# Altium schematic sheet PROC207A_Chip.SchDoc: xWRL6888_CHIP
size 431 x 279 mm; Date: Not shown in title block; ApprovedBy: Not shown in title block; CheckedBy: Not shown in title block; Author: Not shown in title block; CompanyName: Not shown in title block; DrawnBy: Mistral; Engineer: Not shown in title block; Organization: Not shown in title block; Address1: Not shown in title block; Address2: Not shown in title block; Address3: Not shown in title block; Address4: Not shown in title block; DocumentNumber: 1; Revision: Use project parameter SCH_Rev; SheetNumber: 6; SheetTotal: 18; PageSetup: Record=PageOptions¦CenterHorizontal=True¦CenterVertical=True¦PrintScale=1.00¦XCorrection=1.00¦YCorrection=1.00¦PrintKind=0¦BorderSize=5000000¦LeftOffset=0¦BottomOffset=0¦Orientation=2¦PaperLength=1000¦PaperWidth=1000¦Scale=100¦PaperSource=15¦PrintQuality=600¦MediaType=1¦DitherType=10¦PaperKind=Letter¦PrintScaleMode=1
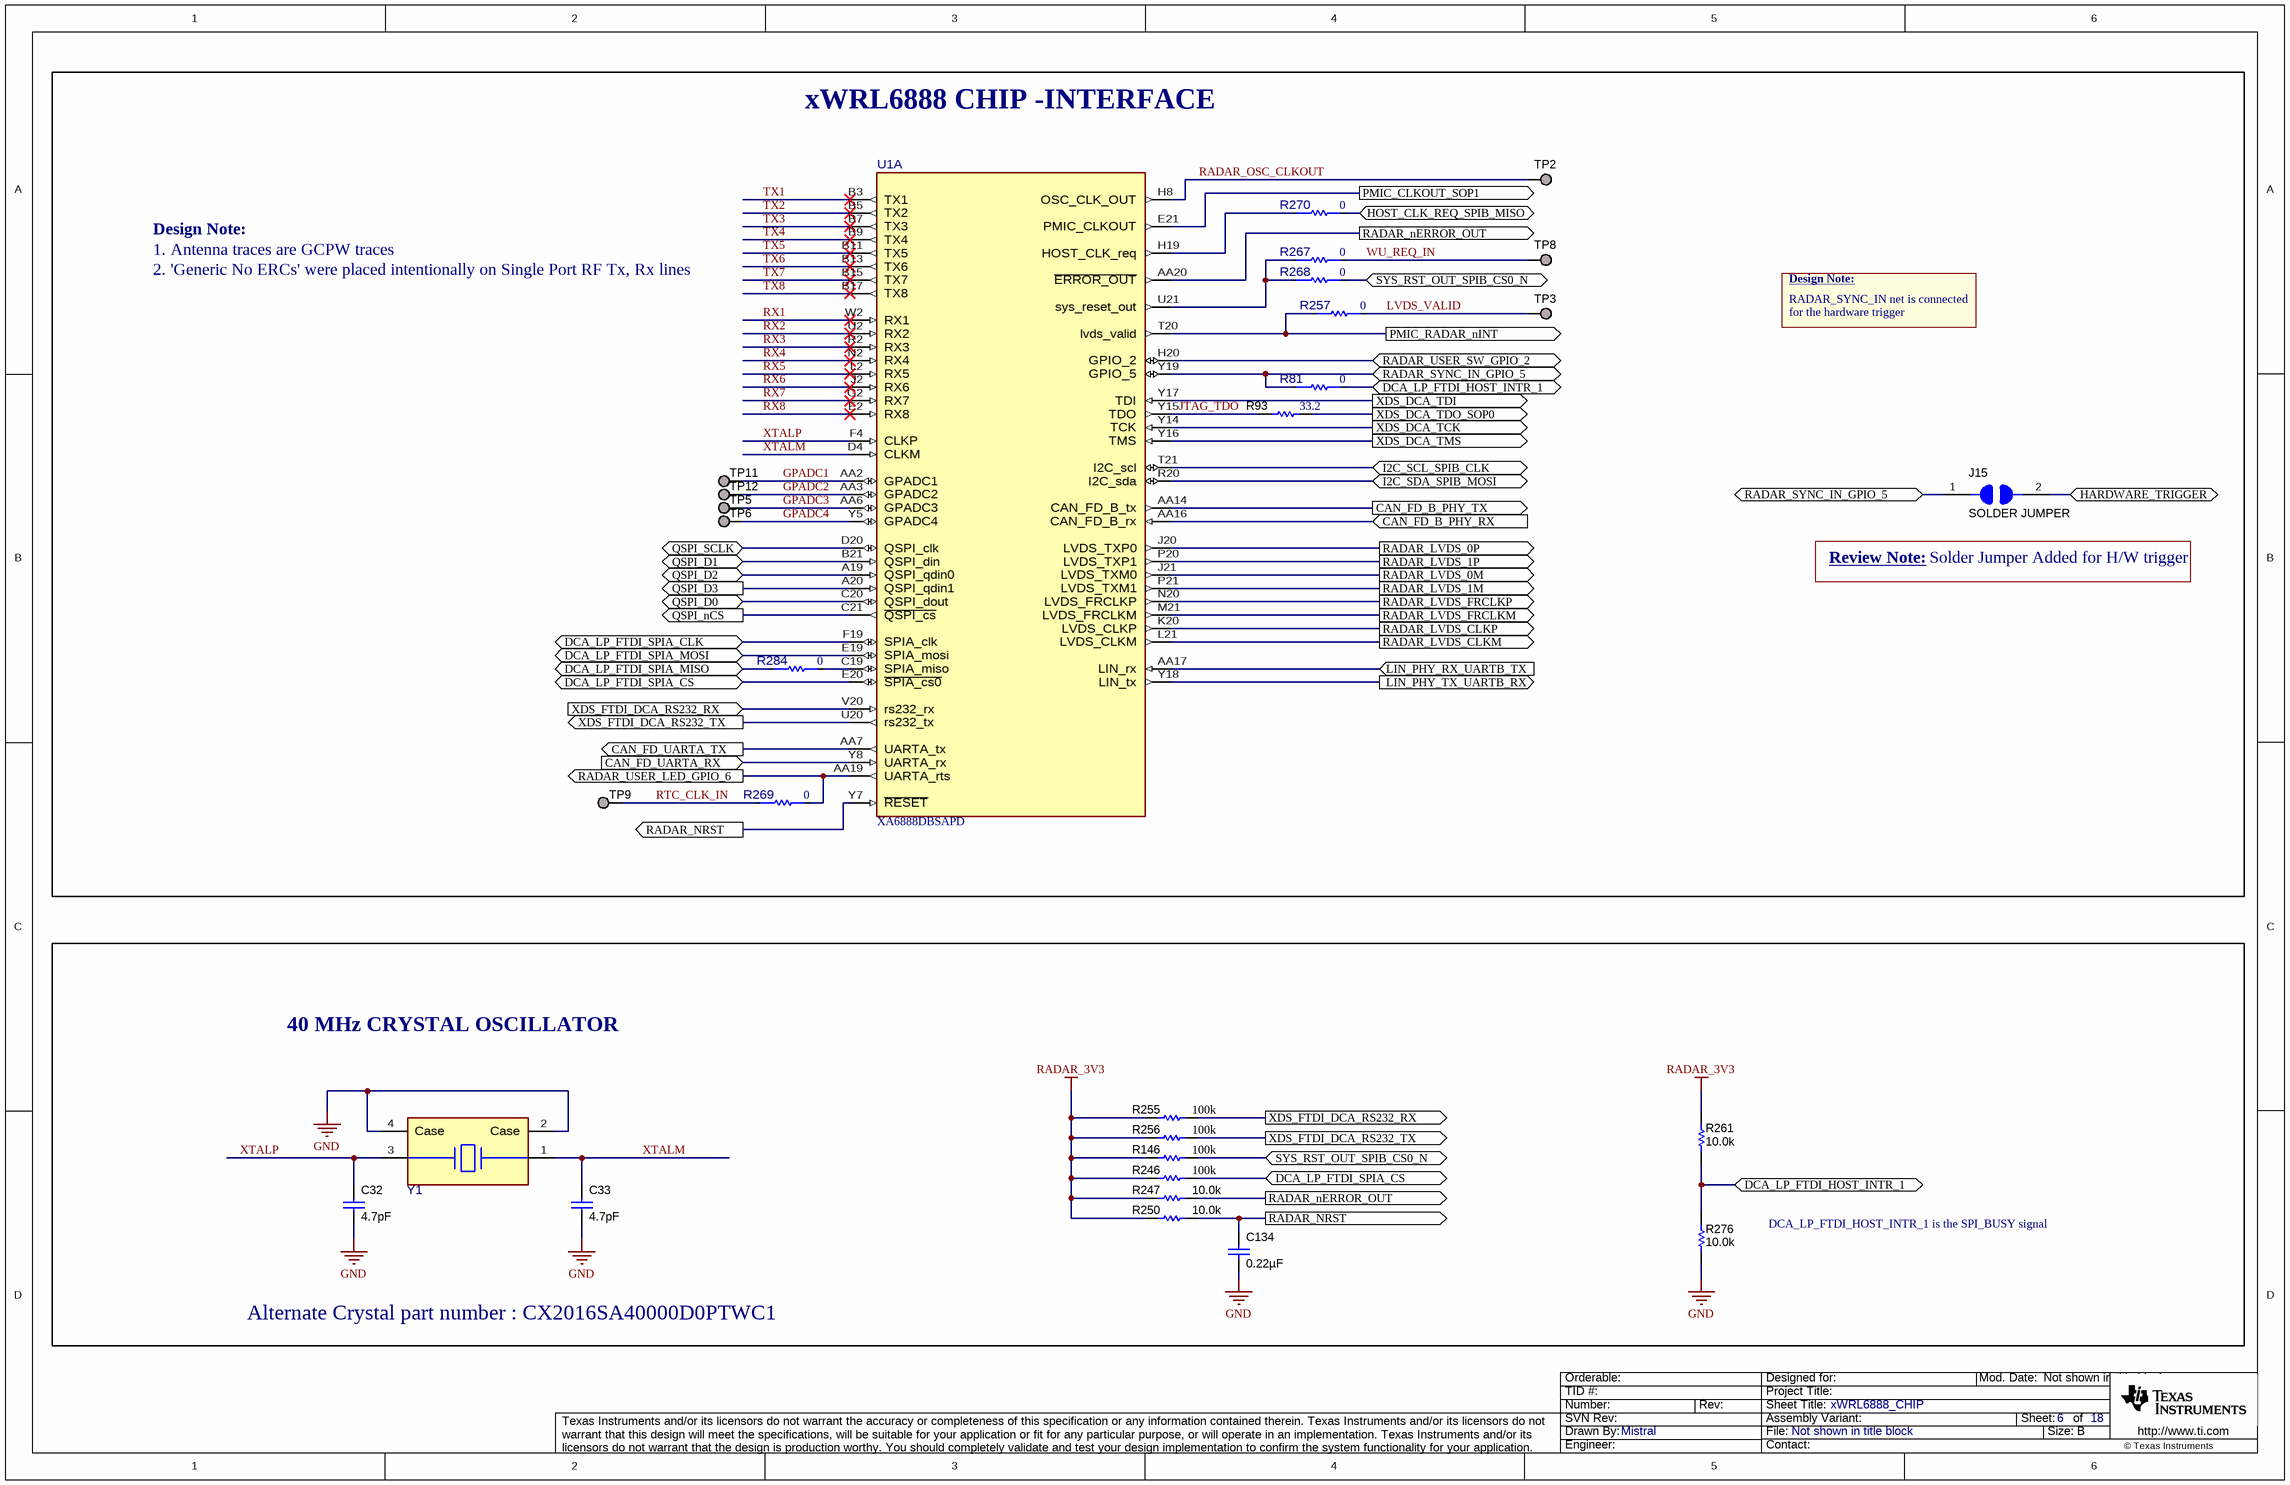
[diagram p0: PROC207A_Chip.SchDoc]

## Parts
C32  ValueDisplayed: 4.7pF  [0402L]  (hidden comment: GJM1555C1H4R7BB01D)
C33  ValueDisplayed: 4.7pF  [0402L]  (hidden comment: GJM1555C1H4R7BB01D)
C134  ValueDisplayed: 0.22µF  [0402L]  (hidden comment: GCM155R71C224KE02D)
J15  SOLDER JUMPER  [SolderJumper]
R81  value 0  [FP-ERJ-2GE0R00X_0402-MFG]  (hidden comment: ERJ-2GE0R00X)
R93  value 33.2  [0402]  (hidden comment: CRCW040233R2FKED)
R146  value 100k  [0402L]  (hidden comment: CRCW0402100KFKED)
R246  value 100k  [0402L]  (hidden comment: CRCW0402100KFKED)
R247  ValueDisplayed: 10.0k  [0402L]  (hidden comment: CRCW040210K0FKED)
R250  ValueDisplayed: 10.0k  [0402L]  (hidden comment: CRCW040210K0FKED)
R255  ValueDisplayed: 100k  [0402L]  (hidden comment: CRCW0402100KFKED)
R256  ValueDisplayed: 100k  [0402L]  (hidden comment: CRCW0402100KFKED)
R257  value 0  [FP-ERJ-2GE0R00X_0402-MFG]  (hidden comment: ERJ-2GE0R00X)
R261  ValueDisplayed: 10.0k  [0402L]  (hidden comment: CRCW040210K0FKED)
R267  value 0  [FP-ERJ-2GE0R00X_0402-MFG]  (hidden comment: ERJ-2GE0R00X)
R268  value 0  [FP-ERJ-2GE0R00X_0402-MFG]  (hidden comment: ERJ-2GE0R00X)
R269  value 0  [FP-ERJ-2GE0R00X_0402-MFG]  (hidden comment: ERJ-2GE0R00X)
R270  value 0  [FP-ERJ-2GE0R00X_0402-MFG]  (hidden comment: ERJ-2GE0R00X)
R276  ValueDisplayed: 10.0k  [0402L]  (hidden comment: CRCW040210K0FKED)
R284  value 0  [FP-ERJ-2GE0R00X_0402-MFG]  (hidden comment: ERJ-2GE0R00X)
TP2  TESTPOINT  [TP_25MIL-SMT]  (value not drawn)  (no BOM)
TP3  TESTPOINT  [TP_25MIL-SMT]  (value not drawn)  (no BOM)
TP5  TESTPOINT  [TP_25MIL-SMT]  (value not drawn)  (no BOM)
TP6  TESTPOINT  [TP_25MIL-SMT]  (value not drawn)  (no BOM)
TP8  TESTPOINT  [TP_25MIL-SMT]  (value not drawn)  (no BOM)
TP9  TESTPOINT  [TP_25MIL-SMT]  (value not drawn)  (no BOM)
TP11  TESTPOINT  [TP_25MIL-SMT]  (value not drawn)  (no BOM)
TP12  TESTPOINT  [TP_25MIL-SMT]  (value not drawn)  (no BOM)
U1  XA6888DBSAPD  [0-MFG]  (part A of 3)
Y1  FW4000044Q  [FP-FW4000044Q_4-SMD-2.0x1.6mm-MFG]  (value not drawn)

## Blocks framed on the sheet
xWRL6888 CHIP -INTERFACE: J15 R81 R93 R257 R267-R270 R284 TP2 TP3 TP5 TP6 TP8 TP9 TP11 TP12 U1

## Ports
CAN_FD_B_PHY_RX (in), CAN_FD_B_PHY_TX (out), CAN_FD_UARTA_RX (in), CAN_FD_UARTA_TX (out), DCA_LP_FTDI_HOST_INTR_1 (bidir), DCA_LP_FTDI_SPIA_CLK (bidir), DCA_LP_FTDI_SPIA_CS (bidir), DCA_LP_FTDI_SPIA_MISO (bidir), DCA_LP_FTDI_SPIA_MOSI (bidir), HARDWARE_TRIGGER (bidir), HOST_CLK_REQ_SPIB_MISO (bidir), I2C_SCL_SPIB_CLK (bidir), I2C_SDA_SPIB_MOSI (bidir), LIN_PHY_RX_UARTB_TX (in), LIN_PHY_TX_UARTB_RX (out), PMIC_CLKOUT_SOP1 (out), PMIC_RADAR_nINT (out), QSPI_D0 (bidir), QSPI_D1 (bidir), QSPI_D2 (bidir), QSPI_D3 (out), QSPI_nCS (out), QSPI_SCLK (bidir), RADAR_LVDS_0M (out), RADAR_LVDS_0P (out), RADAR_LVDS_1M (out), RADAR_LVDS_1P (out), RADAR_LVDS_CLKM (out), RADAR_LVDS_CLKP (out), RADAR_LVDS_FRCLKM (out), RADAR_LVDS_FRCLKP (out), RADAR_nERROR_OUT (out), RADAR_NRST (out), RADAR_SYNC_IN_GPIO_5 (bidir), RADAR_USER_LED_GPIO_6 (out), RADAR_USER_SW_GPIO_2 (bidir), SYS_RST_OUT_SPIB_CS0_N (bidir), XDS_DCA_TCK (out), XDS_DCA_TDI (out), XDS_DCA_TDO_SOP0 (out), XDS_DCA_TMS (out), XDS_FTDI_DCA_RS232_RX (in), XDS_FTDI_DCA_RS232_RX (out), XDS_FTDI_DCA_RS232_TX (out)

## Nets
GND: C32.1 C33.1 C134.1 R276.2 Y1.2(Case) Y1.4(Case)
RADAR_3V3: R146.2 R246.2 R247.2 R250.2 R255.2 R256.2 R261.1
CAN_FD_B_PHY_RX: U1.AA16(CAN_FD_B_rx) ; port CAN_FD_B_PHY_RX
CAN_FD_B_PHY_TX: U1.AA14(CAN_FD_B_tx) ; port CAN_FD_B_PHY_TX
CAN_FD_UARTA_RX: U1.Y8(UARTA_rx) ; port CAN_FD_UARTA_RX
CAN_FD_UARTA_TX: U1.AA7(UARTA_tx) ; port CAN_FD_UARTA_TX
DCA_LP_FTDI_HOST_INTR_1: R81.2 R261.2 R276.1 ; port DCA_LP_FTDI_HOST_INTR_1
DCA_LP_FTDI_SPIA_CLK: U1.F19(SPIA_clk) ; port DCA_LP_FTDI_SPIA_CLK
DCA_LP_FTDI_SPIA_CS: R246.1 U1.E20(~{SPIA_cs0}) ; port DCA_LP_FTDI_SPIA_CS
DCA_LP_FTDI_SPIA_MISO: R284.1 ; port DCA_LP_FTDI_SPIA_MISO
DCA_LP_FTDI_SPIA_MOSI: U1.E19(SPIA_mosi) ; port DCA_LP_FTDI_SPIA_MOSI
GPADC1: TP11.1 U1.AA2(GPADC1)
GPADC2: TP12.1 U1.AA3(GPADC2)
GPADC3: TP5.1 U1.AA6(GPADC3)
GPADC4: TP6.1 U1.Y5(GPADC4)
HARDWARE_TRIGGER: J15.2 ; port HARDWARE_TRIGGER
HOST_CLK_REQ_SPIB_MISO: R270.2 ; port HOST_CLK_REQ_SPIB_MISO
I2C_SCL_SPIB_CLK: U1.T21(I2C_scl) ; port I2C_SCL_SPIB_CLK
I2C_SDA_SPIB_MOSI: U1.R20(I2C_sda) ; port I2C_SDA_SPIB_MOSI
JTAG_TDO: R93.2 U1.Y15(TDO)
LIN_PHY_RX_UARTB_TX: U1.AA17(LIN_rx) ; port LIN_PHY_RX_UARTB_TX
LIN_PHY_TX_UARTB_RX: U1.Y18(LIN_tx) ; port LIN_PHY_TX_UARTB_RX
LVDS_VALID: R257.2 TP3.1
PMIC_CLKOUT_SOP1: U1.E21(PMIC_CLKOUT) ; port PMIC_CLKOUT_SOP1
PMIC_RADAR_nINT: R257.1 U1.T20(lvds_valid) ; port PMIC_RADAR_nINT
QSPI_D0: U1.C20(QSPI_dout) ; port QSPI_D0
QSPI_D1: U1.B21(QSPI_din) ; port QSPI_D1
QSPI_D2: U1.A19(QSPI_qdin0) ; port QSPI_D2
QSPI_D3: U1.A20(QSPI_qdin1) ; port QSPI_D3
QSPI_nCS: U1.C21(~{QSPI_cs}) ; port QSPI_nCS
QSPI_SCLK: U1.D20(QSPI_clk) ; port QSPI_SCLK
RADAR_LVDS_0M: U1.J21(LVDS_TXM0) ; port RADAR_LVDS_0M
RADAR_LVDS_0P: U1.J20(LVDS_TXP0) ; port RADAR_LVDS_0P
RADAR_LVDS_1M: U1.P21(LVDS_TXM1) ; port RADAR_LVDS_1M
RADAR_LVDS_1P: U1.P20(LVDS_TXP1) ; port RADAR_LVDS_1P
RADAR_LVDS_CLKM: U1.L21(LVDS_CLKM) ; port RADAR_LVDS_CLKM
RADAR_LVDS_CLKP: U1.K20(LVDS_CLKP) ; port RADAR_LVDS_CLKP
RADAR_LVDS_FRCLKM: U1.M21(LVDS_FRCLKM) ; port RADAR_LVDS_FRCLKM
RADAR_LVDS_FRCLKP: U1.N20(LVDS_FRCLKP) ; port RADAR_LVDS_FRCLKP
RADAR_nERROR_OUT: R247.1 U1.AA20(~{ERROR_OUT}) ; port RADAR_nERROR_OUT
RADAR_NRST: C134.2 R250.1 U1.Y7(~{RESET}) ; port RADAR_NRST
RADAR_OSC_CLKOUT: TP2.1 U1.H8(OSC_CLK_OUT)
RADAR_SYNC_IN_GPIO_5: J15.1 R81.1 U1.Y19(GPIO_5) ; port RADAR_SYNC_IN_GPIO_5
RADAR_USER_LED_GPIO_6: R269.2 U1.AA19(UARTA_rts) ; port RADAR_USER_LED_GPIO_6
RADAR_USER_SW_GPIO_2: U1.H20(GPIO_2) ; port RADAR_USER_SW_GPIO_2
RTC_CLK_IN: R269.1 TP9.1
RX1: U1.W2(RX1)
RX2: U1.U2(RX2)
RX3: U1.R2(RX3)
RX4: U1.N2(RX4)
RX5: U1.L2(RX5)
RX6: U1.J2(RX6)
RX7: U1.G2(RX7)
RX8: U1.E2(RX8)
SYS_RST_OUT_SPIB_CS0_N: R146.1 R268.2 ; port SYS_RST_OUT_SPIB_CS0_N
TX1: U1.B3(TX1)
TX2: U1.B5(TX2)
TX3: U1.B7(TX3)
TX4: U1.B9(TX4)
TX5: U1.B11(TX5)
TX6: U1.B13(TX6)
TX7: U1.B15(TX7)
TX8: U1.B17(TX8)
WU_REQ_IN: R267.2 TP8.1
XDS_DCA_TCK: U1.Y14(TCK) ; port XDS_DCA_TCK
XDS_DCA_TDI: U1.Y17(TDI) ; port XDS_DCA_TDI
XDS_DCA_TDO_SOP0: R93.1 ; port XDS_DCA_TDO_SOP0
XDS_DCA_TMS: U1.Y16(TMS) ; port XDS_DCA_TMS
XDS_FTDI_DCA_RS232_RX: R255.1 U1.V20(rs232_rx) ; port XDS_FTDI_DCA_RS232_RX
XDS_FTDI_DCA_RS232_TX: R256.1 U1.U20(rs232_tx) ; port XDS_FTDI_DCA_RS232_TX
XTALM: C33.2 U1.D4(CLKM) Y1.1(1_Xtal)
XTALP: C32.2 U1.F4(CLKP) Y1.3(2_Xtal)
NetR267_1: R267.1 R268.1 U1.U21(sys_reset_out)
NetR270_1: R270.1 U1.H19(HOST_CLK_req)
NetR284_2: R284.2 U1.C19(SPIA_miso)

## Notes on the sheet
- 1. Antenna traces are GCPW traces
- 2. 'Generic No ERCs' were placed intentionally on Single Port RF Tx, Rx lines
- Design Note:
- RADAR_SYNC_IN net is connected
- for the hardware trigger
- Review Note:
- Solder Jumper Added for H/W trigger
- 40 MHz CRYSTAL OSCILLATOR
- DCA_LP_FTDI_HOST_INTR_1 is the SPI_BUSY signal
- Alternate Crystal part number : CX2016SA40000D0PTWC1

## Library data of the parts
C32 C33 = CMP-0006367-2: CAP, CERM, 4.7 pF, 50 V, +/- 2%, C0G/NP0, 0402; Manufacturer: MuRata; TaMin_C: -55°C; Polarized: N; SizeAreaWB_mm2: 3; Value1: Unknown; U/M: EA; Value: 4.7pF; TaMax_C: 125°C; SizeZ_mm: 0.6; SizeX_mm: 1; SizeY_mm: 0.5; Cap_Case: 0402; Value2: 50V; CompType: Capacitor; AEC Category: Q200
C134 = CMP-0078265-1: CAP, CERM, 0.22 µF, 16 V,+/- 10%, X7R, AEC-Q200 Grade 1, 0402; Manufacturer: MuRata; TaMin_C: -55°C; Polarized: N; SizeAreaWB_mm2: 3; U/M: EA; Value: 0.22uF; TaMax_C: 125°C; SizeZ_mm: 0.6; SizeX_mm: 1; SizeY_mm: 0.5; Cap_Case: 0402; Value2: 16V; CompType: Capacitor; AEC Qualified: Y; Cap_F: 220nF; AEC Category: Q200
J15 = CMP-0080367-2: Solder Jumper, SMT; Manufacturer: NA
R81 R257 R267-R270 R284 = CMP-0002710-1: 0 Ohms Jumper Chip Resistor 0402 (1005 Metric) Automotive AEC-Q200 Thick Film; Manufacturer: Panasonic; SizeZ_mm: 0.4mm; AEC Qualified: Yes; AEC Grade: Grade 0; Power: 100mW
R93 = CMP-0026299-2: RES, 33.2, 1%, 0.063 W, AEC-Q200 Grade 0, 0402; Manufacturer: Vishay-Dale; AEC Qualified: Y; Power_W: 63mW; SizeZ_mm: 0.6; TempCo: 100 ppm/C; VDC_V: 50V; AEC Category: Q200; AEC Grade: 0; EIA_Code: E96; SizeArea_mm2: 0.5; SizeX_mm: 1; Value2: 0.063W; Value_Code: 33R2
R146 R246 = CMP-0025950-3: RES, 100 k, 1%, 0.063 W, AEC-Q200 Grade 0, 0402; Manufacturer: Vishay-Dale; Power_W: 63mW; TempCo: 100 ppm/C; EIA_Code: E96; SizeX_mm: 1; SizeY_mm: 0.5; SizeZ_mm: 0.6; Value2: 0.063W; AEC Qualified: Y; VDC_V: 50V; AEC Category: Q200; AEC Grade: 0
R247 R250 R261 R276 = CMP-0025958-3: RES, 10.0 k, 1%, 0.063 W, AEC-Q200 Grade 0, 0402; Manufacturer: Vishay-Dale; Power_W: 63mW; TempCo: 100 ppm/C; Value_Code: 10k0; Value: 10.0k; EIA_Code: E96; Res_ohm: 10k; SizeX_mm: 1; SizeY_mm: 0.5; SizeZ_mm: 0.6; Value2: 0.063W; AEC Qualified: Y; VDC_V: 50V; AEC Category: Q200; AEC Grade: 0
R255 R256 = CMP-0025950-3: RES, 100 k, 1%, 0.063 W, AEC-Q200 Grade 0, 0402; Manufacturer: Vishay-Dale; Power_W: 63mW; TempCo: 100 ppm/C; Value: 100k; EIA_Code: E96; SizeX_mm: 1; SizeY_mm: 0.5; SizeZ_mm: 0.6; Value2: 0.063W; AEC Qualified: Y; VDC_V: 50V; AEC Category: Q200; AEC Grade: 0
TP2 TP3 TP5 TP6 TP8 TP9 TP11 TP12 = CMP-0078143-3: TEST POINT.  No entry in BOM.
U1 = CMP-0122984-4: Manufacturer: Texas Instruments; SizeZ_mm: 1.044mm; AEC Qualified: Unknown; Standoff Height: 0.155mm; AEC Category: Q200; CompType: IC
Y1 = CMP-0090505-1: 40MHz ±10ppm Crystal 8pF 50 Ohms 4-SMD, No Lead; Manufacturer: Diodes; Alternate Part Number: CX2016SA40000D0PTWC1; Frequency Stability: 50ppm; Esr: 50; AEC Qualified: Yes; AEC Grade: Grade 1; SizeZ_mm: 0.55mm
